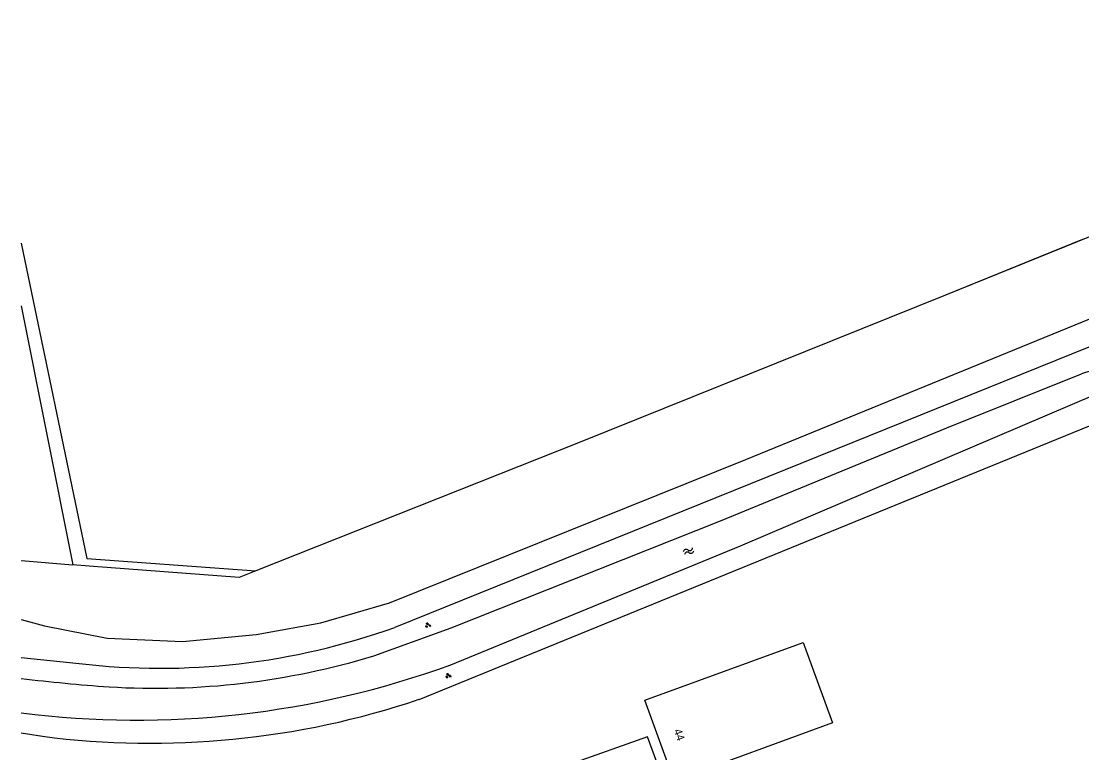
# Model space of a CAD drawing. Extents: x 135999 to 138000, y 396000 to 398501.
# Drawn here: x 136000 to 136159, y 396578.8 to 396688.4 of the extents above; entities that cross this region are included whole.
import ezdxf

# ---------------------------------------------------------------- set-up
doc = ezdxf.new("R2010")
doc.units = 0
for name, color, linetype in [('gg-afsc-erfafscheiding', 7, 'Continuous'), ('gg-afsc-hekwerk', 7, 'Continuous'), ('gg-bbg-bassin', 7, 'Continuous'), ('gg-knt-bronhoudergrens', 7, 'Continuous'), ('gg-kntw-bovenkant insteek waterloop', 7, 'Continuous'), ('gg-kntw-waterlijn', 7, 'Continuous'), ('gt-anno-plantopografie huisnummer', 7, 'Continuous'), ('gt-bbg-plantopografie pand', 7, 'Continuous'), ('gt-grn-groengrens', 7, 'Continuous'), ('gt-symb-groenvak', 7, 'Continuous'), ('gt-symb-watersymbool', 7, 'Continuous')]:
    doc.layers.add(name, color=color, linetype=linetype)

# ---------------------------------------------------------------- blocks, each defined once
blk = doc.blocks.new('gt0-WA')
at = {"layer": 'gt-symb-watersymbool'}
for centre, start, end in [((-0.32, 0.02), 28.0725, 151.9275), ((0.43, 0.42), 208.0725, 331.9275), ((-0.32, -0.43), 28.0725, 151.9275), ((0.43, -0.03), 208.0725, 331.9275)]:
    blk.add_arc(centre, 0.425, start, end, dxfattribs=at)
blk = doc.blocks.new('gt0-GRVAK')
at = {"layer": 'gt-symb-groenvak'}
for p, q in [((-0.11, 0.19), (-0.23, 0.24)), ((-0.18, 0.15), (0.09, 0.15)), ((-0.09, 0.21), (-0.16, 0.32)), ((-0.05, 0.21), (-0.05, 0.39)), ((0, 0.21), (0.06, 0.32)), ((0.02, 0.19), (0.13, 0.24)), ((0.26, -0.05), (0.2, 0.06)), ((0.3, -0.05), (0.3, 0.13)), ((0.35, -0.05), (0.41, 0.06)), ((-0.24, -0.23), (-0.36, -0.18)), ((-0.32, -0.26), (-0.05, -0.26)), ((-0.23, -0.21), (-0.29, -0.1)), ((-0.18, -0.2), (-0.18, -0.02)), ((-0.14, -0.21), (-0.07, -0.1)), ((-0.12, -0.23), (0, -0.18)), ((0.24, -0.07), (0.12, -0.02)), ((0.17, -0.11), (0.44, -0.11)), ((0.37, -0.07), (0.49, -0.02))]:
    blk.add_line(p, q, dxfattribs=at)

msp = doc.modelspace()

# ---------------------------------------------------------------- linework, layer by layer
at = {"layer": 'gg-afsc-erfafscheiding'}
msp.add_line((136000, 396607.61), (136007.76, 396606.96), dxfattribs=at)
at = {"layer": 'gg-afsc-hekwerk'}
for p in [(136000, 396645.8), (136010.2, 396606.77)]:
    msp.add_line(p, (136007.76, 396606.96), dxfattribs=at)
for points in [[(136238.62, 396688.44), (136164.36, 396657.83), (136138.54, 396647.37), (136083.79, 396625.36), (136035.19, 396606.06)], [(136159.11, 396655.71), (136138.54, 396647.37), (136083.79, 396625.36), (136035.19, 396606.06)], [(136035.19, 396606.06), (136032.65, 396605.05), (136010.2, 396606.77)]]:
    msp.add_lwpolyline(points, dxfattribs=at)
at = {"layer": 'gg-bbg-bassin'}
msp.add_lwpolyline([(136077.62, 396568.74), (136091.89, 396574.15), (136091.26, 396575.97), (136095.26, 396577.38), (136093.89, 396581.19), (136070.82, 396572.98), (136071.63, 396570.86), (136073.11, 396571.34), (136074.16, 396568.49), (136075.68, 396569.01)], dxfattribs=at)
at = {"layer": 'gg-knt-bronhoudergrens'}
for p, q in [((136000, 396655.19), (136009.85, 396607.91)), ((136009.85, 396607.91), (136035.19, 396606.06))]:
    msp.add_line(p, q, dxfattribs=at)
at = {"layer": 'gg-kntw-bovenkant insteek waterloop'}
for p, q in [((136059.66, 396586.8), (136166.39, 396630.36)), ((136000, 396593.06), (136008.67, 396592.17)), ((136000, 396581.76), (136003.2, 396581.27))]:
    msp.add_line(p, q, dxfattribs=at)
msp.add_lwpolyline([(136182.88, 396634.73), (136176.05, 396637.89), (136173.73, 396638.62), (136168.77, 396640.49), (136165.67, 396640.86), (136162.65, 396640.66), (136055.99, 396597.58)], dxfattribs=at)
for centre, radius, start, end in [((136020.82, 396695.47), 104.01, 263.2926, 289.7671), ((136019.43, 396706.43), 126.21, 262.6105, 288.5884)]:
    msp.add_arc(centre, radius, start, end, dxfattribs=at)
at = {"layer": 'gg-kntw-waterlijn'}
for points in [[(136052.88, 396593.33), (136064.46, 396597.5), (136104.83, 396613.54), (136138.78, 396627.51), (136158.92, 396635.61)], [(136064.39, 396591.98), (136107.81, 396609.83), (136165.08, 396634.22)]]:
    msp.add_lwpolyline(points, dxfattribs=at)
for centre, radius, start, end in [((136163.1, 396623.47), 12.83, 73.5829, 108.987), ((136017.25, 396721.7), 138.02, 262.8183, 289.9712), ((136020.14, 396700.87), 112.41, 266.452, 286.931), ((136035.41, 396892.96), 305.1, 263.3353, 265.8222)]:
    msp.add_arc(centre, radius, start, end, dxfattribs=at)
at = {"layer": 'gt-bbg-plantopografie pand'}
msp.add_lwpolyline([(136093.46, 396586.66), (136117.2, 396595.34), (136121.61, 396583.27), (136097.88, 396574.59), (136093.46, 396586.66)], dxfattribs=at)
at = {"layer": 'gt-grn-groengrens'}
msp.add_lwpolyline([(136000, 396598.79), (136003.48, 396597.84), (136012.87, 396595.98), (136024.2, 396595.46), (136035.24, 396596.5), (136044.93, 396598.29), (136055.22, 396601.27), (136108.61, 396622.75), (136160.21, 396643.85)], dxfattribs=at)

# ---------------------------------------------------------------- block references
at = {"layer": 'gt-symb-groenvak'}
for p in [(136060.96, 396597.91), (136064, 396590.35)]:
    msp.add_blockref('gt0-GRVAK', p, dxfattribs=at)
at = {"layer": 'gt-symb-watersymbool', "rotation": 23.07822140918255}
msp.add_blockref('gt0-WA', (136099.98, 396608.97), dxfattribs=at)

# ---------------------------------------------------------------- texts
at = {"layer": 'gt-anno-plantopografie huisnummer'}
msp.add_text('44', height=1.2, rotation=290.0838, dxfattribs=at).set_placement((136097.78, 396582.14))

doc.saveas('drawing.dxf')
